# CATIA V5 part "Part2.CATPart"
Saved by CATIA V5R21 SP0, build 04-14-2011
Part number: Part2
Bounding box of the stored display mesh (mm): x 0 to 20, y -69.015 to 69.015, z 7.835 to 66.136
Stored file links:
  D:\CATIA V5R21 E-RESOURCES\CATIA-V5R21\catia-v5r21-Prts\c16_catia_v5r21_prt\Slide Curve Joint-(Fig16-40)\Part2.CATPart
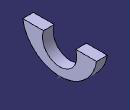
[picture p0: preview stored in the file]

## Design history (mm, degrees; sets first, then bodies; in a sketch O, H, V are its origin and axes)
Body1 (main body)
  Sketch1 on yz-plane, origin (0, 0, 0), H (0, 1, 0), V (0, 0, 1)
    arc A1 centre (0, 77.8354) radius 70 from (-69.0153, 66.1355) to (69.0153, 66.1355) ccw
    point P1 (0, 77.8354)
    point P2 (-69.0153, 66.1355)
    point P3 (69.0153, 66.1355)
    arc A2 centre (0, 55) radius 32 from (-30, 66.1355) to (30, 66.1355) ccw
    point P4 (0, 55)
    point P5 (-30, 66.1355)
    point P6 (30, 66.1355)
    line L1 (30, 66.1355) -> (69.0153, 66.1355)
    point P7 (69.0153, 66.1355)
    line L2 (-30, 66.1355) -> (-69.0153, 66.1355)
    point P8 (-69.0153, 66.1355)
    reference intersected line E1 through (0, 0) direction (-1, 0) from xy-plane
    reference intersected line E3 through (0, 0) direction (0, 1) from zx-plane
    radius A1 = 70
    radius A2 = 32
    distance P6 P7 = 39.0153
    distance P6 E3 = 30
    distance P4 H = 55
    coincidence: P1 V, P4 V, P7 P3, P8 A1, P2 P8, L2 L1, E3 P1, P2 L1, P3 L1, P5 L1, P6 L2
    horizontal: L1 H, L2 H, E1 H
    vertical: E3 V
    perpendicularity: E3 L1
  Pad1: profile Sketch1, direction (1, 0, 0), length 20
  Point1: type OnCurve, Support edge [face of Pad1 from Sketch1.A1 | end face of Pad1], Ratio 0.5
  Sketch2 on yz-plane, origin (0, 0, 0), H (0, 1, 0), V (0, 0, 1)
    line L1 (0, 81.1355) -> (0, 51.1355)
    point P1 (0, 81.1355)
    reference projected line E1 (69.0153, 66.1355) -> (30, 66.1355) from edge [face of Pad1 from Sketch1.L1 | end face of Pad1]
    length L1 = 30
    distance E1 P1 = 15
    coincidence: P1 V
    vertical: L1 V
